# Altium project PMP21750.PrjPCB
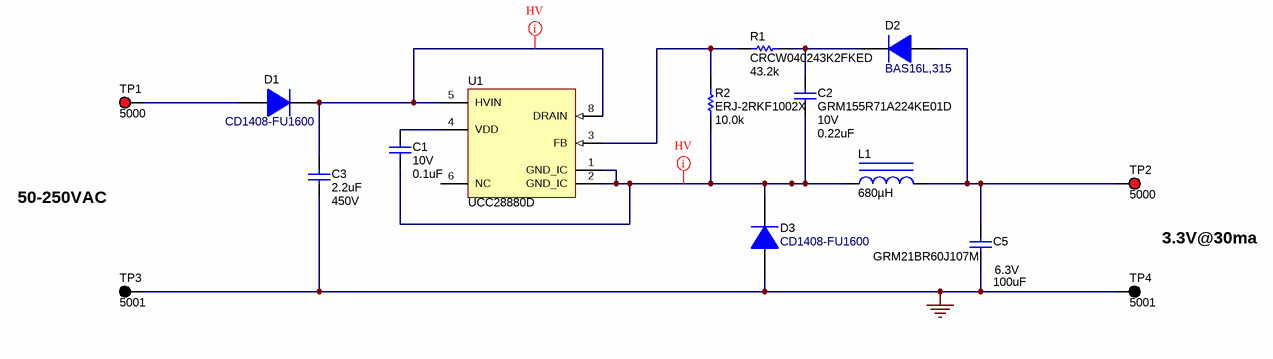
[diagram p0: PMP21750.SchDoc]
TechSupport: http://www.ti.com/support; SCH_Rev: A; PRJ_Title: UCC28880 High-side Buck Converter; PRJ_Number: PMP21750; PRJ_Engineer: Jason Kriek; PRJ_Customer: Public Release; PCB_Rev: A; PCB_Layout: Neal Tatum; CopyrightYear: 2018
1 sheet, 15 parts. Net scope: global (net labels, ports and power ports of the same name join across sheets).
Board file: PMP21750.PcbDoc

## Sheet PMP21750.SchDoc: US line to 5V/35mA
size 431 x 279 mm; Date: Not shown in title block; ApprovedBy: Not shown in title block; CheckedBy: Not shown in title block; Author: Not shown in title block; CompanyName: Not shown in title block; DrawnBy: S Yu; Engineer: Not shown in title block; Organization: Not shown in title block; Address1: Not shown in title block; Address2: Not shown in title block; Address3: Not shown in title block; Address4: Not shown in title block; DocumentNumber: 1; Revision: Use project parameter SCH_Rev; SheetNumber: 1; SheetTotal: 1; PageSetup: Record=PageOptions¦CenterHorizontal=True¦CenterVertical=True¦PrintScale=1.00¦XCorrection=1.00¦YCorrection=1.00¦PrintKind=0¦BorderSize=5000000¦LeftOffset=0¦BottomOffset=0¦Orientation=2¦PaperLength=1000¦PaperWidth=1000¦Scale=100¦PaperSource=15¦PrintQuality=600¦MediaType=1¦DitherType=10¦PaperKind=Letter¦PrintScaleMode=1

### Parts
C1  VDC_V: 10V  ValueDisplayed: 0.1uF  [0603S]  (hidden comment: C0603C104K8RACTU)
C2  GRM155R71A224KE01D  VDC_V: 10V  ValueDisplayed: 0.22uF  [0402S]
C3  ValueDisplayed: 2.2uF  VDC_V: 450V  [2220_280L]  (hidden comment: Capacitor)
C5  GRM21BR60J107M  VDC_V: 6.3V  ValueDisplayed: 100uF  [0805L]
D1  CD1408-FU1600  [Diode_1408]
D2  BAS16L,315  [SOD882]
D3  CD1408-FU1600  [Diode_1408]
L1  ValueDisplayed: 680µH  [WE-LQ_1812]  (hidden comment: 744045681)
R1  CRCW040243K2FKED  ValueDisplayed: 43.2k  [0402S]
R2  ERJ-2RKF1002X  ValueDisplayed: 10.0k  [0402S]
TP1  5000  [Keystone5000]
TP2  5000  [Keystone5000]
TP3  5001  [Keystone5001]
TP4  5001  [Keystone5001]
U1  UCC28880D  [D0007A_N]

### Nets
GND: C3.2 C5.2 D3.2(A) TP3.1 TP4.1
NetC1_1: C1.1 U1.4(VDD)
NetC1_2: C1.2 C2.2 D3.1(K) L1.1 R2.1 U1.1(GND_IC) U1.2(GND_IC)
NetC2_1: C2.1 D2.1(K) R1.2
NetC3_1: C3.1 D1.1(K) U1.5(HVIN) U1.8(DRAIN)
NetC5_1: C5.1 D2.2(A) L1.2 TP2.1
NetD1_2: D1.2(A) TP1.1
NetR1_1: R1.1 R2.2 U1.3(FB)

Not connected (* = marked no-connect by the designer): U1 6(NC)

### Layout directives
net class HV: NetC1_2, NetC3_1

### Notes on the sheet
- 50-250VAC
- 3.3V@30ma

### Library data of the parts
C1 = CMP-0006862-5: CAP, CERM, 0.1 uF, 10 V, +/- 10%, X7R, 0603; Manufacturer: Kemet; TaMin_C: -55°C; Polarized: N; SizeAreaWB_mm2: 4.68; Value1: Unknown; U/M: EA; Value: 0.1uF; TaMax_C: 125°C; SizeZ_mm: 1; SizeX_mm: 1.6; SizeY_mm: 0.8; Cap_Case: 0603; SizeArea_mm2: 1.28; Cap_F: 100nF; AEC Category: Q200
C2 = CMP-0006630-2: CAP, CERM, 0.22 uF, 10 V, +/- 10%, X7R, 0402; Manufacturer: MuRata; TaMin_C: -55°C; Polarized: N; SizeAreaWB_mm2: 3; Value1: Unknown; U/M: EA; Value: 0.22uF; TaMax_C: 125°C; SizeZ_mm: 0.6; SizeX_mm: 1; SizeY_mm: 0.5; Cap_Case: 0402; CompType: Capacitor; Cap_F: 220nF; AEC Category: Q200
C3 = CMP-0009372-2: CAP, CERM, 2.2 uF, 450 V, +/- 10%, X6S, 2220; PartNumber: C5750X6S2W225K250KA; Manufacturer: TDK; Polarized: N; Value: 2.2uF; U/M: EA; Cap_F: 2.2µF; Value1: Unknown; TaMin_C: -55°C; TaMax_C: 105°C; Cap_Case: 2220; SizeArea_mm2: 28.5; SizeAreaWB_mm2: 53.9; SizeX_mm: 5.7; SizeY_mm: 5; SizeZ_mm: 2.8; AEC Category: Q200
C5 = CMP-0008280-2: CAP, CERM, 100 uF, 6.3 V, +/- 20%, X5R, 0805; Manufacturer: MuRata; TaMin_C: -55°C; Polarized: N; SizeAreaWB_mm2: 6.75; Value1: Unknown; U/M: EA; Value: 100uF; TaMax_C: 85°C; SizeZ_mm: 1.45; SizeX_mm: 2; SizeY_mm: 1.25; Cap_Case: 0805; SizeArea_mm2: 2.5; CompType: Capacitor; Cap_F: 100µF; AEC Category: Q200
D1 D3 = CMP-0029015-1: Diode, Ultrafast, 600 V, 1 A, 1408 Diode; Manufacturer: Bourns; Io_A: 1A; Green_Lifecycle: Not Set; SizeAreaWB_mm2: 12.76; Vr_V: 600V; Green_REACh: Incomplete; TJmax_C: 175°C; U/M: EA; Value: 600V; SizeZ_mm: 1.15; SizeX_mm: 3.4; SizeY_mm: 1.9; Vf_V: 1.25V; SizeArea_mm2: 6.46; AEC Qualified: N; AEC Category: Q101; RJC_CperW: 40
D2 = CMP-0076954-1: Diode, Switching, 100 V, 0.215 A, SOD882; Manufacturer: Nexperia; SizeAreaWB_mm2: 3.146225; Vr_V: 100V; SizeArea_mm2: 0.576225; TJmax_C: 150°C; AEC Category: Q101; Value: 100V; SizeZ_mm: 0.5; Green_REACh: Incomplete; Io_A: 215mA; Vf_V: 1.25V; SizeY_mm: 0.585; Green_Lifecycle: Not Set; U/M: EA; Value1: 0.215A; SizeX_mm: 0.985
L1 = CMP-0084743-1: Inductor, Wirewound, Ferrite, 680 µH, 0.09 A, 16.8 ohm, SMD; Manufacturer: Wurth Elektronik; Imax_A: 90mA; AEC Category: Q200; Isat: 0.2A @ 20% inductance drop; SizeZ_mm: 2.9; SizeY_mm: 3.2; Value: 680uH; Value2: 0.09A; DCR_ohm: 16.8; SizeX_mm: 4.5; Irms: 0.09A @ 40C rise; SizeArea_mm2: 14.4; SizeAreaWB_mm2: 23.1; AEC Qualified: N
R1 = CMP-0026379-2: RES, 43.2 k, 1%, 0.063 W, AEC-Q200 Grade 0, 0402; Manufacturer: Vishay-Dale; Power_W: 63mW; TempCo: 100 ppm/C; Value_Code: 43k2; Value: 43.2k; EIA_Code: E96; SizeX_mm: 1; SizeY_mm: 0.5; SizeZ_mm: 0.6; Value2: 0.063W; AEC Qualified: Y; VDC_V: 50V; AEC Category: Q200; AEC Grade: 0
R2 = CMP-0026658-1: RES, 10.0 k, 1%, 0.1 W, 0402; Manufacturer: Panasonic; Power_W: 100mW; TempCo: 100 ppm/C; Value_Code: 10k0; U/M: EA; Value: 10.0k; EIA_Code: E96; Res_ohm: 10k; SizeX_mm: 1; SizeY_mm: 0.5; SizeZ_mm: 0.6; Value2: 0.1W; VDC_V: 50V; AEC Category: Q200
TP1 TP2 = CMP-0055137-1: Test Point, Miniature, Red, TH; Manufacturer: Keystone; CNHeader: FALSE; ContactFinish: Silver; CT: TRUE; Green_Lifecycle: Active; Green_REACh: Passed
TP3 TP4 = CMP-0055138-1: Test Point, Miniature, Black, TH; Manufacturer: Keystone; CNHeader: FALSE; ContactFinish: Silver; CT: TRUE; Green_Lifecycle: Active; Green_REACh: Passed
U1 = UCC28880D: Low Quiescent Current Switcher IC for AC/DC Power Supplies, D0007A; Alternate Manufacturer: None; Manufacturer: Texas Instruments; SymbolCreator: a0411947; U/M: EA

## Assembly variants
001: all parts fitted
